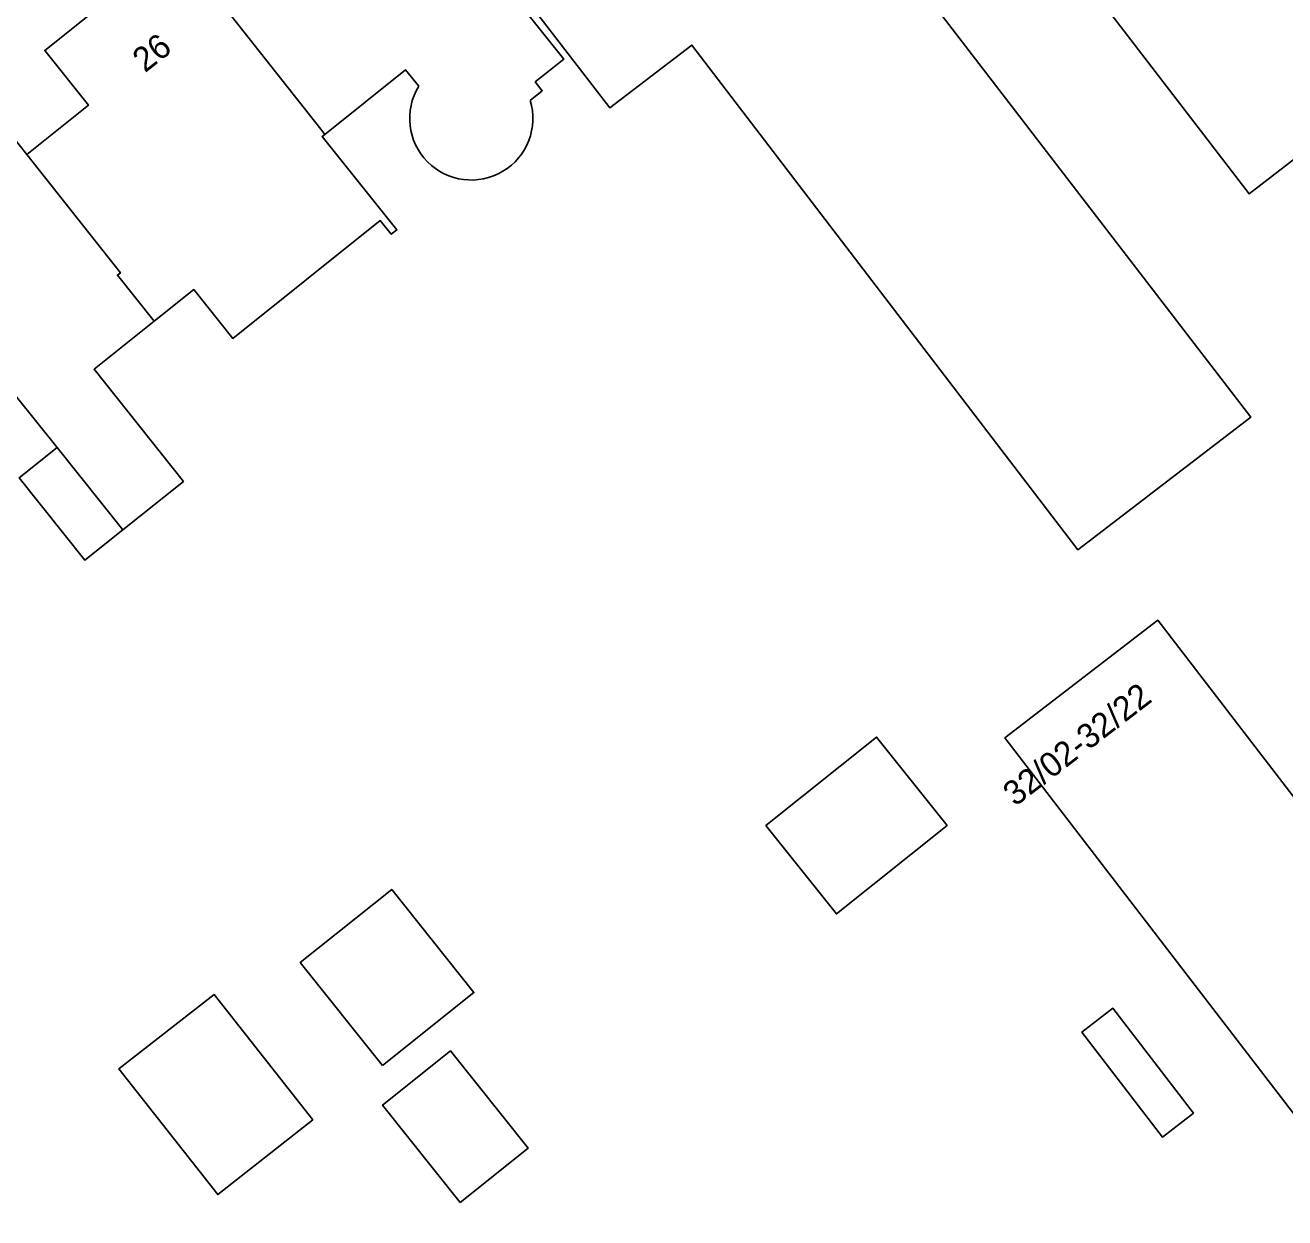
# Model space of a CAD drawing. Extents: x 161771 to 163125, y 382475 to 383179.
# Drawn here: x 162011.1 to 162062.6, y 382870.2 to 382918.9 of the extents above; entities that cross this region are included whole.
import ezdxf

# ---------------------------------------------------------------- set-up
doc = ezdxf.new("R2010")
doc.units = 0
for name, color, linetype in [('IMGEO_Erf', 7, 'Continuous'), ('IMGEO_Pand', 7, 'Continuous'), ('IMGEO_Pand_nummerreeks', 7, 'Continuous')]:
    doc.layers.add(name, color=color, linetype=linetype)

msp = doc.modelspace()

# ---------------------------------------------------------------- linework, layer by layer
at = {"layer": 'IMGEO_Erf'}
for points in [[(162043.125, 382926.473), (162061.259, 382902.902), (162054.176, 382897.478), (162038.39, 382918.114), (162035.035, 382915.547), (162030.61, 382921.288)], [(162051.197, 382889.784), (162057.452, 382894.592), (162063.969, 382886.113), (162071.515, 382876.245), (162075.187, 382879.066), (162066.693, 382890.12), (162071.612, 382893.899), (162067.649, 382899.278), (162071.852, 382902.522), (162063.278, 382913.648), (162061.185, 382912.038), (162051.955, 382924.053)], [(162029.478, 382922.14), (162033.148, 382917.543), (162031.979, 382916.61), (162032.266, 382916.251), (162031.77, 382915.855)], [(162009.324, 382915.953), (162011.172, 382913.639), (162013.696, 382915.655), (162011.905, 382917.898), (162014.627, 382920.071)], [(162027.209, 382916.432), (162026.672, 382917.104), (162023.368, 382914.466), (162023.261, 382914.38), (162026.312, 382910.559), (162026.085, 382910.378), (162025.636, 382910.94), (162019.602, 382906.123), (162018.009, 382908.119), (162016.386, 382906.823), (162013.922, 382904.856), (162017.579, 382900.275), (162015.103, 382898.298), (162013.542, 382897.052), (162010.858, 382900.414), (162012.408, 382901.652), (162009.903, 382904.77)], [(162067.761, 382868.227), (162051.197, 382889.784)]]:
    msp.add_lwpolyline(points, dxfattribs=at)
for points in [[(162044.298, 382882.583), (162041.413, 382886.195), (162045.943, 382889.812), (162048.828, 382886.2)], [(162025.725, 382876.378), (162022.358, 382880.594), (162026.103, 382883.584), (162029.469, 382879.369)], [(162018.984, 382871.105), (162014.932, 382876.246), (162018.84, 382879.286), (162022.87, 382874.162)], [(162054.345, 382877.751), (162055.608, 382878.722), (162058.907, 382874.429), (162057.644, 382873.458)], [(162028.906, 382870.781), (162025.727, 382874.762), (162028.504, 382876.98), (162031.683, 382872.999)]]:
    msp.add_lwpolyline(points, close=True, dxfattribs=at)
msp.add_arc((162029.36, 382915.118), 2.521, 148.5688, 17.0112, dxfattribs=at)
at = {"layer": 'IMGEO_Pand'}
for points in [[(162043.125, 382926.473), (162042.333, 382925.863), (162040.442, 382928.32), (162042.82, 382930.15), (162043.59, 382930.742), (162043.376, 382931.027), (162043.048, 382931.499), (162034.516, 382942.573), (162030.916, 382939.795), (162024.72, 382935.013), (162028.097, 382930.608), (162025.213, 382928.29), (162030.61, 382921.288), (162035.035, 382915.547), (162038.39, 382918.114), (162054.176, 382897.478), (162061.259, 382902.902)], [(162069.783, 382919.527), (162067.792, 382917.998), (162058.989, 382929.457), (162051.955, 382924.053), (162061.185, 382912.038), (162063.278, 382913.648), (162071.852, 382902.522), (162077.336, 382906.735), (162078.775, 382907.841)], [(162023.261, 382914.38), (162023.368, 382914.466), (162023.204, 382914.684), (162017.28, 382922.175), (162016.605, 382921.637), (162015.825, 382921.943), (162014.503, 382920.887), (162014.627, 382920.071), (162011.905, 382917.898), (162013.696, 382915.655), (162011.172, 382913.639), (162015, 382908.802), (162014.882, 382908.708), (162016.386, 382906.823), (162018.009, 382908.119), (162019.602, 382906.123), (162025.636, 382910.94), (162026.085, 382910.378), (162026.312, 382910.559)], [(162012.408, 382901.652), (162015.103, 382898.298), (162017.579, 382900.275), (162013.922, 382904.856), (162016.386, 382906.823), (162014.882, 382908.708), (162015, 382908.802), (162011.172, 382913.639), (162009.324, 382915.953), (162004.368, 382912.029), (162009.921, 382905.018), (162009.788, 382904.912), (162009.903, 382904.77)], [(162012.408, 382901.652), (162010.858, 382900.414), (162013.542, 382897.052), (162015.103, 382898.298)], [(162057.452, 382894.592), (162051.197, 382889.784), (162067.761, 382868.227), (162082.588, 382879.645), (162076.982, 382886.924), (162076.854, 382887.091), (162071.612, 382893.899), (162066.693, 382890.12), (162075.187, 382879.066), (162071.515, 382876.245), (162063.969, 382886.113)], [(162041.413, 382886.195), (162044.298, 382882.583), (162048.828, 382886.2), (162045.943, 382889.812)], [(162025.725, 382876.378), (162029.469, 382879.369), (162026.103, 382883.584), (162022.358, 382880.594)], [(162014.932, 382876.246), (162018.984, 382871.105), (162022.87, 382874.162), (162018.84, 382879.286)], [(162057.644, 382873.458), (162058.907, 382874.429), (162055.608, 382878.722), (162054.345, 382877.751)], [(162028.906, 382870.781), (162031.683, 382872.999), (162028.504, 382876.98), (162025.727, 382874.762)]]:
    msp.add_lwpolyline(points, close=True, dxfattribs=at)
for points in [[(162029.478, 382922.14), (162025.62, 382926.972), (162023.645, 382925.395), (162022.771, 382926.491), (162020.055, 382924.323), (162019.222, 382924.65), (162017.832, 382923.54), (162017.957, 382922.716), (162017.28, 382922.175), (162023.204, 382914.684), (162023.368, 382914.466), (162026.672, 382917.104), (162027.209, 382916.432)], [(162031.77, 382915.855), (162032.266, 382916.251), (162031.979, 382916.61), (162033.148, 382917.543), (162029.478, 382922.14)]]:
    msp.add_lwpolyline(points, dxfattribs=at)
msp.add_arc((162029.36, 382915.118), 2.521, 148.5688, 17.0112, dxfattribs=at)

# ---------------------------------------------------------------- texts
at = {"layer": 'IMGEO_Pand_nummerreeks'}
for s, rotation, p in [('26', 38.3366, (162016.007, 382916.961)), ('32/02-32/22', 37.5459, (162051.614, 382886.951))]:
    msp.add_text(s, height=1, rotation=rotation, dxfattribs=at).set_placement(p)

doc.saveas('drawing.dxf')
